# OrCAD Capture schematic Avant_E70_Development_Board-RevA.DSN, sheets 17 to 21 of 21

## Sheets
17 Power Supplies 2: size D; title: Power Supplies 2
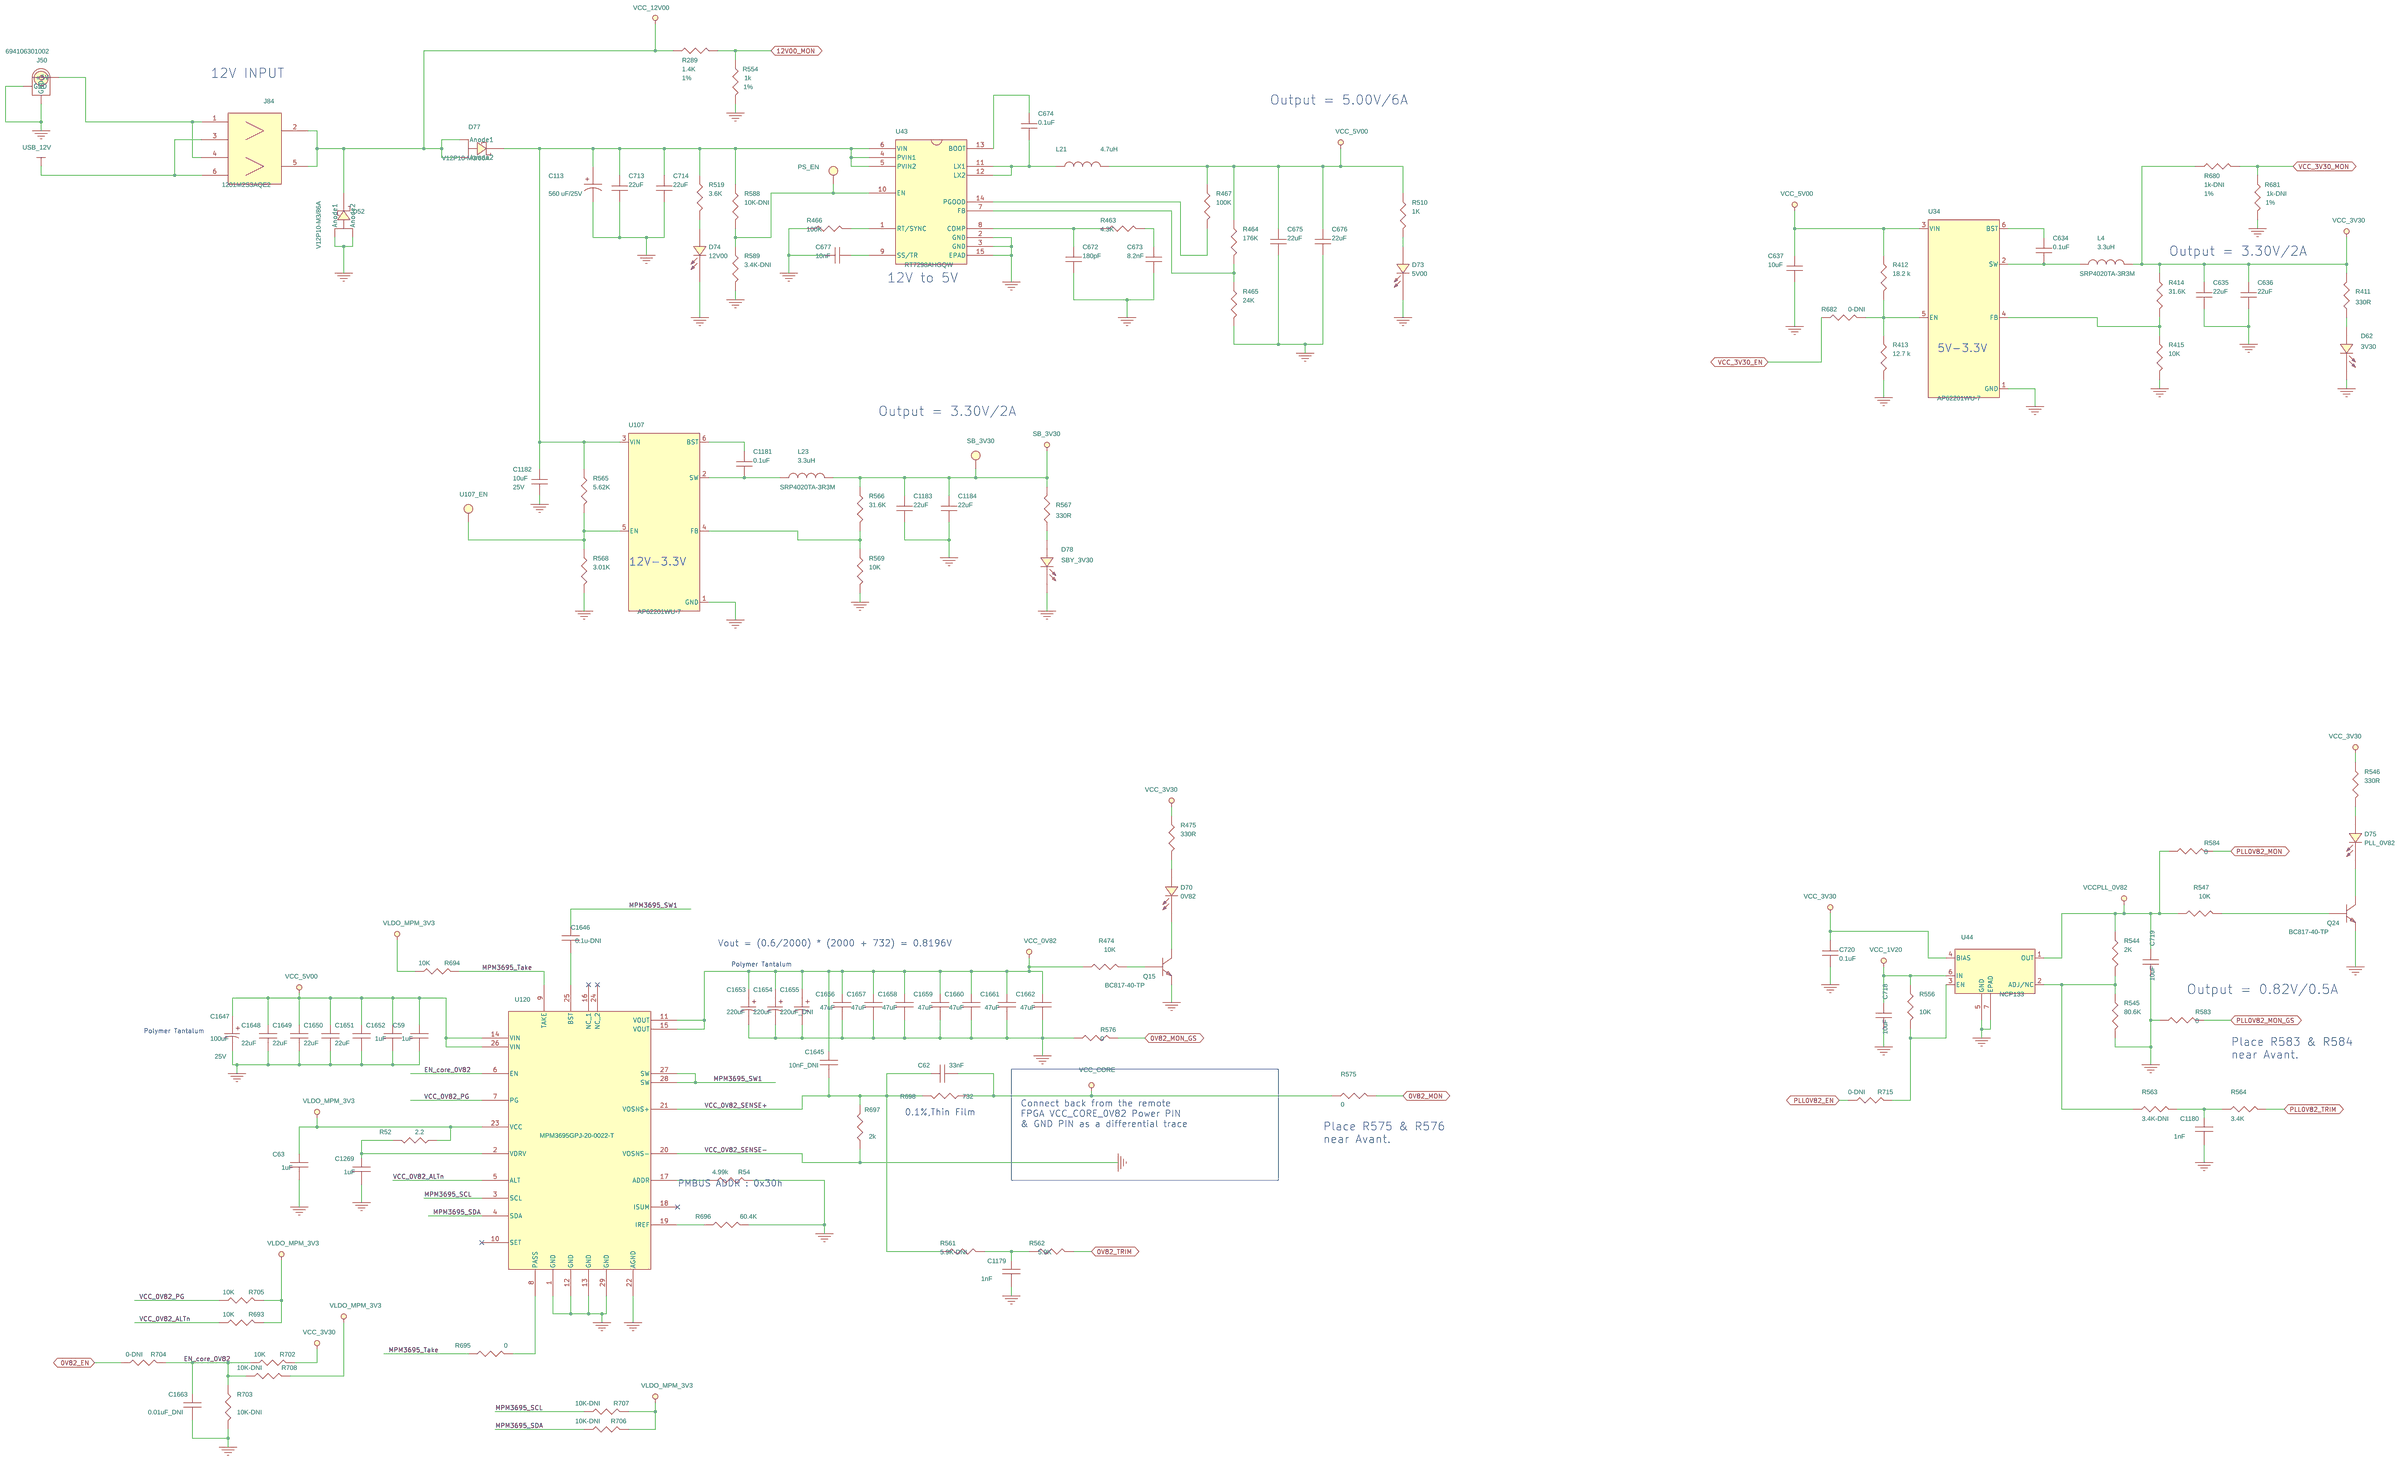
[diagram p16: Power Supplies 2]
18 Ground: size B; title: Ground
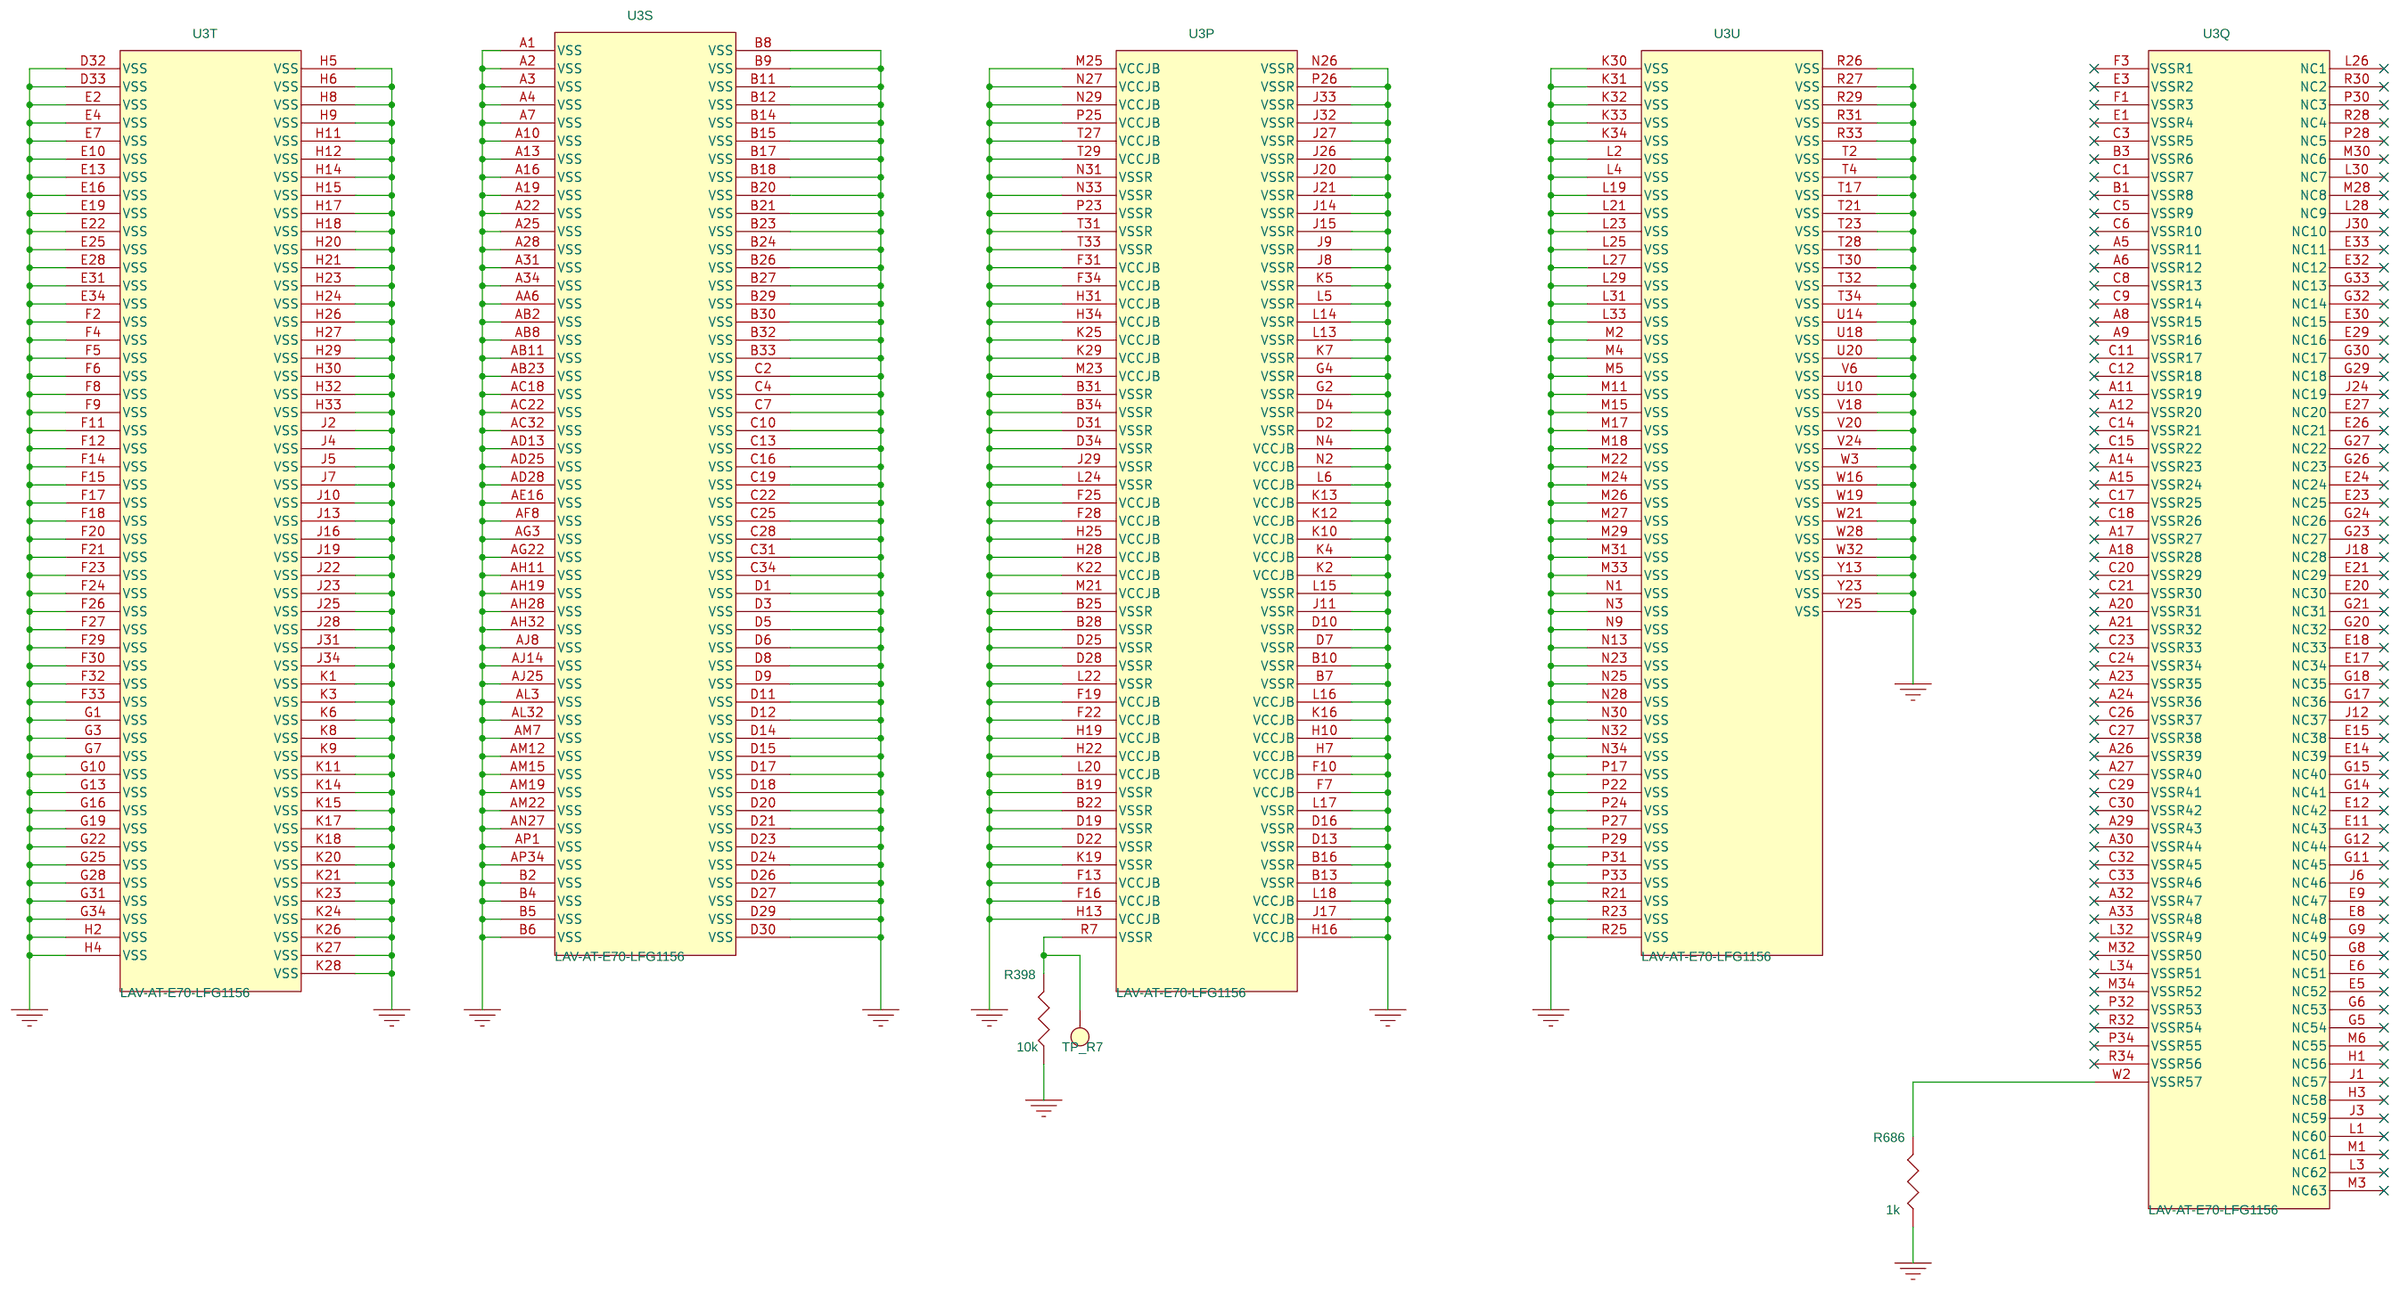
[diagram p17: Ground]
19 Platform Manager 2: size C; title: Platfrom Manager 2
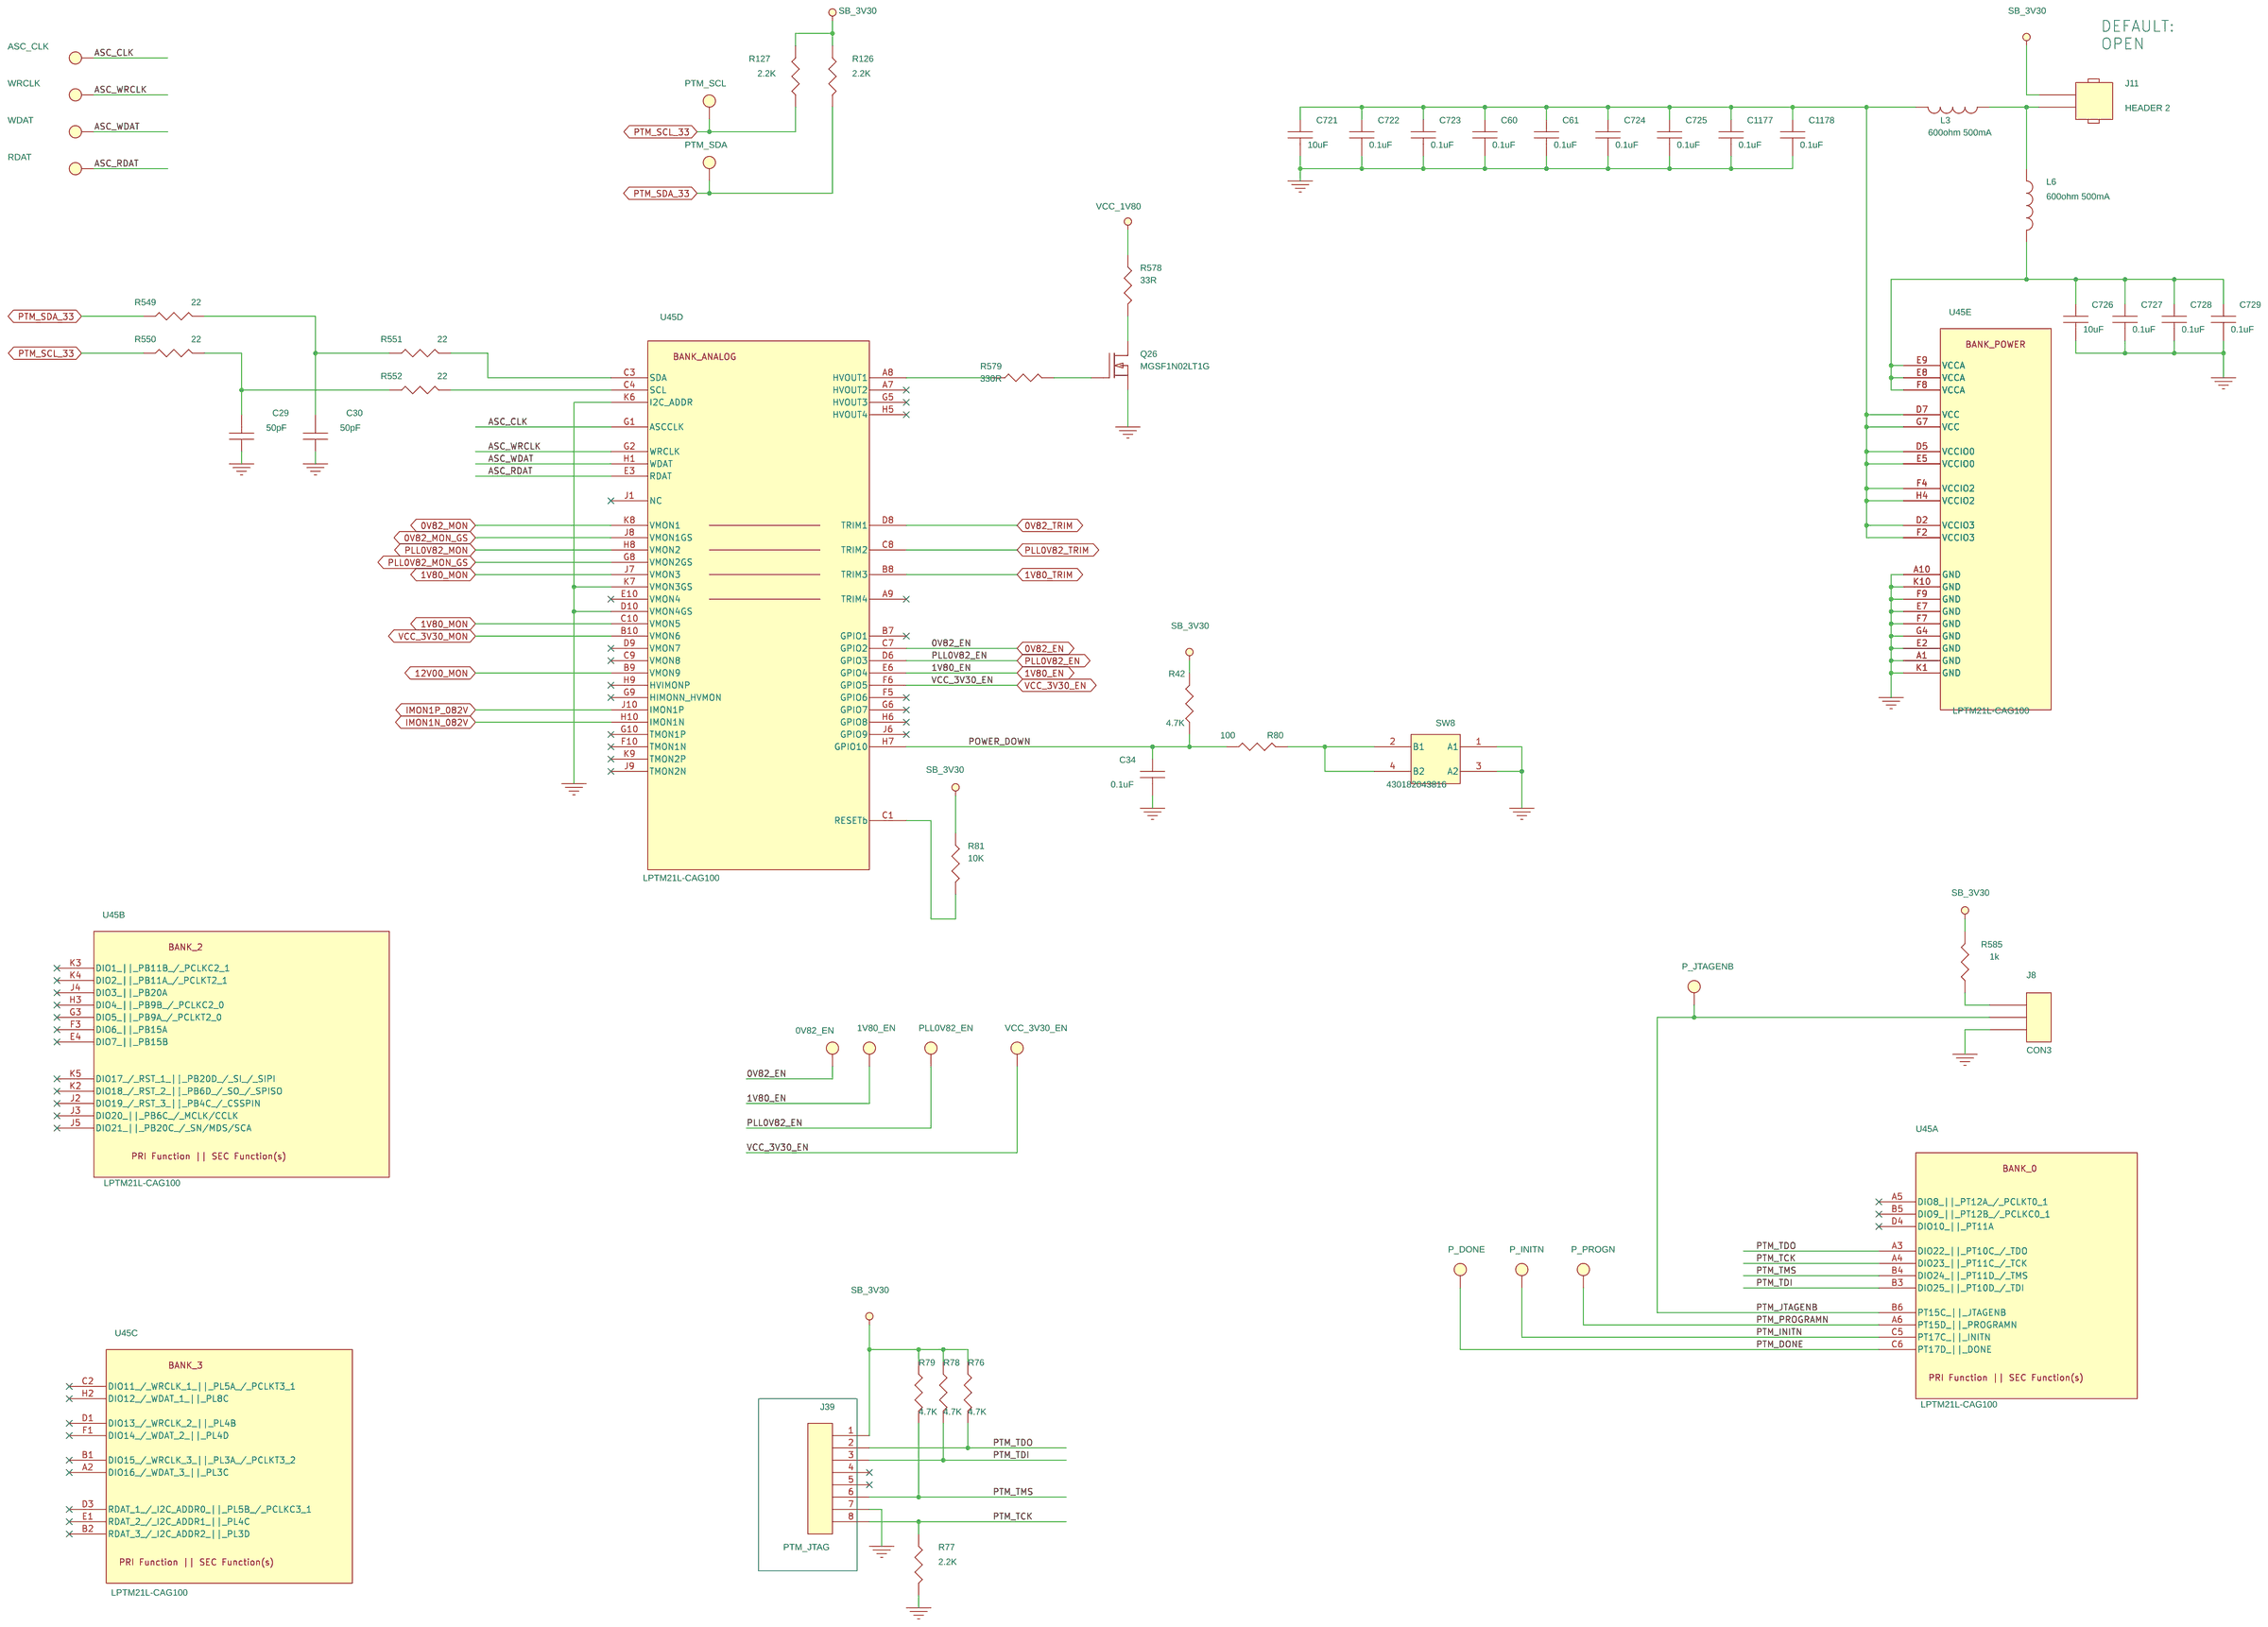
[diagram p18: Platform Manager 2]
20 USB Power Sink: size B; title: USB Power Sink
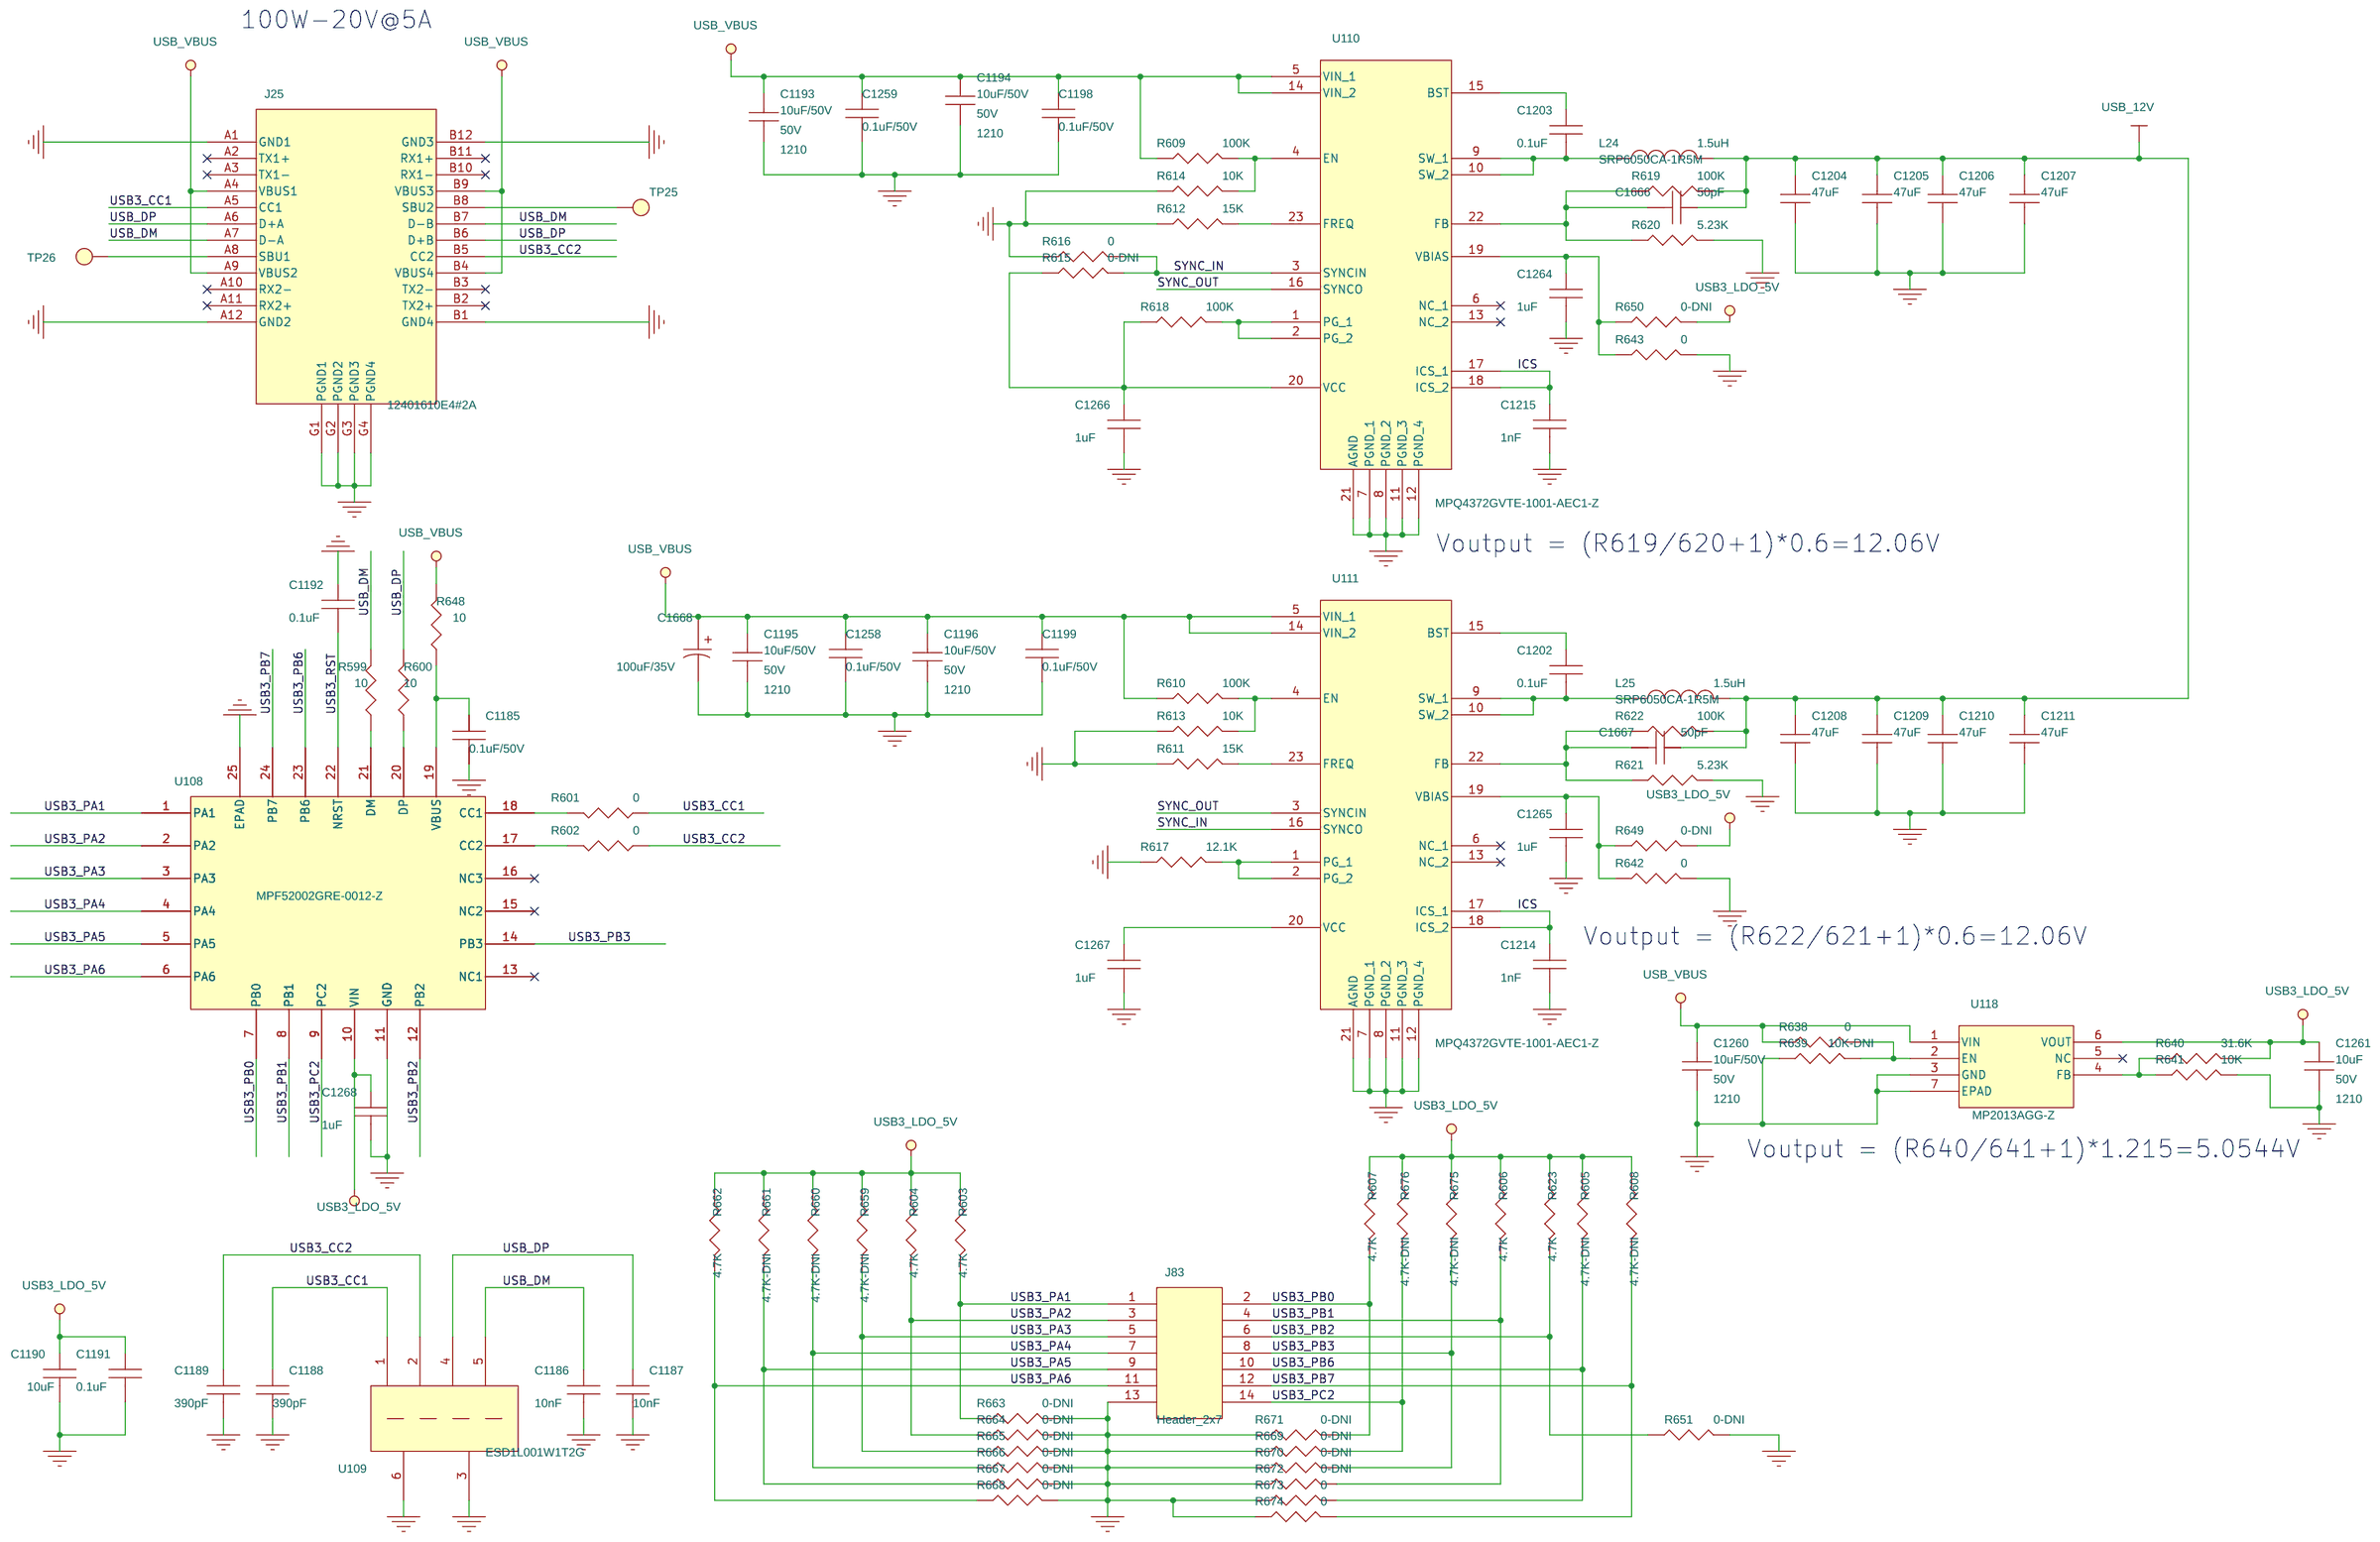
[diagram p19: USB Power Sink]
21 Power Block Diagram: title: Power Block Diagram
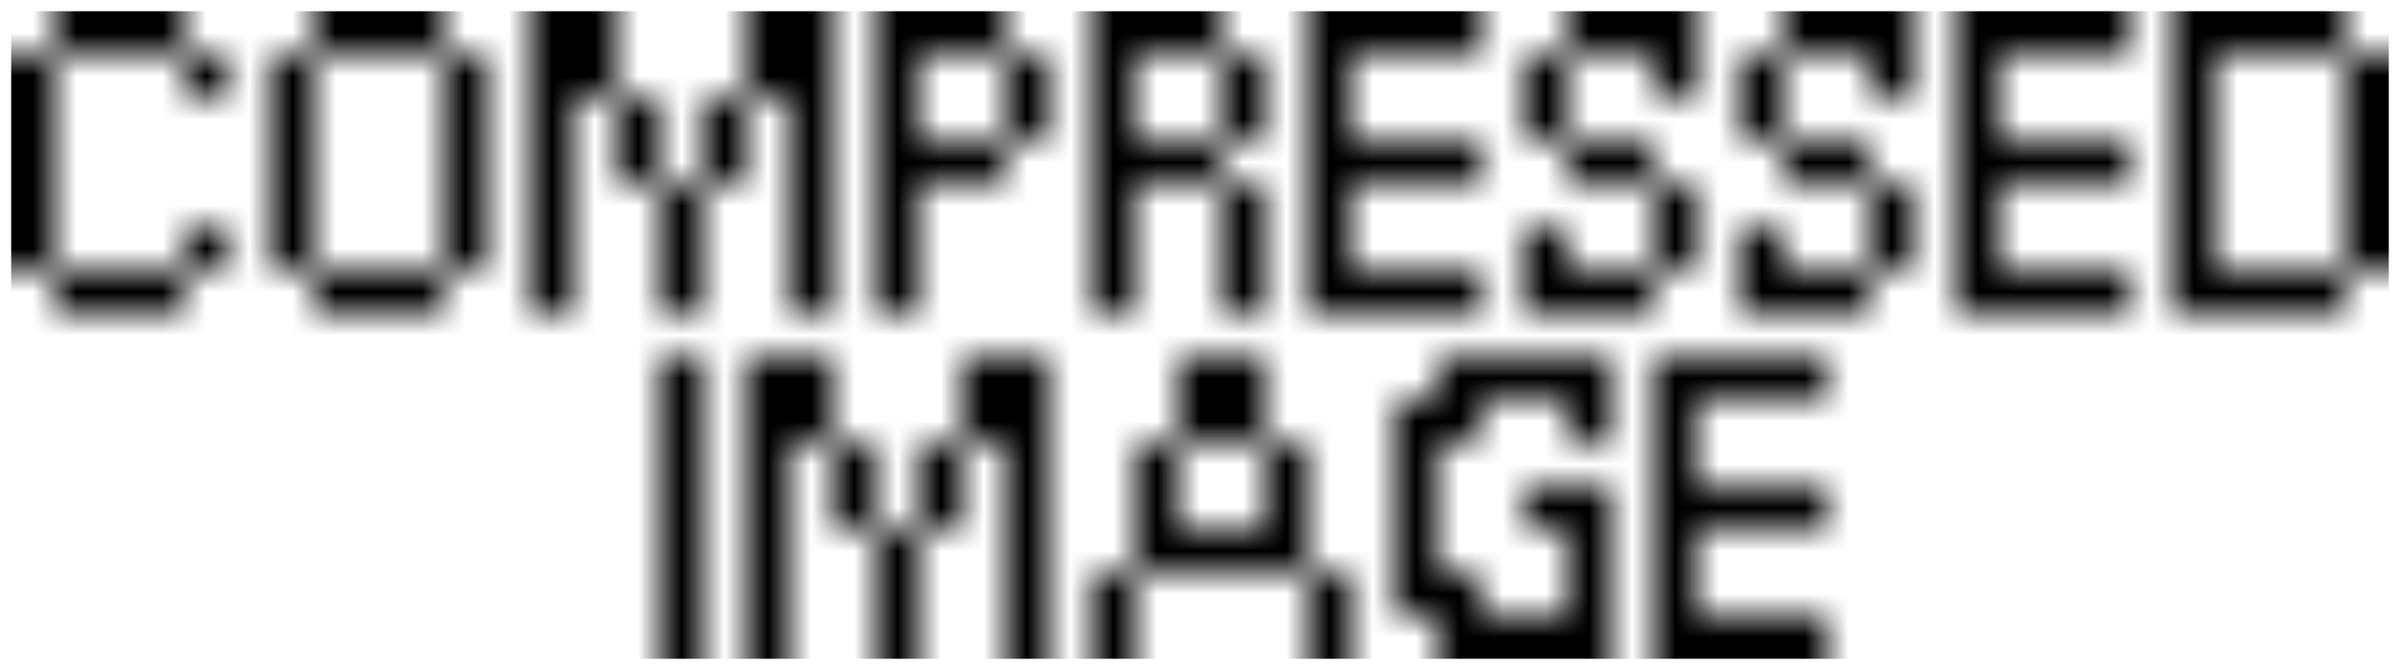
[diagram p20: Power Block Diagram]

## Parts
sheet Bank-12,13 PMODs
U3  LAV-AT-E70-LFG1156  [LAV-AT-500-L_1156]  (sections A,B,C,D,E,F,G,H,I,J,K,L,M,N,O,P,Q,R,S,T,U)
sheet Ground
R398  10k  [R0402]
R686  1k  [R0402]
TP_R7  T POINT R  [TP]
sheet Platform Manager 2
0V82_EN  T POINT R  [TP]
1V80_EN  T POINT R  [TP]
ASC_CLK  VTTVREF  [TP_50]
C29  50pF  [C0603]
C30  50pF  [C0603]
C34  0.1uF  [C0201]
C60  0.1uF  [C0402]
C61  0.1uF  [C0402]
C721  10uF  [C0402]
C722  0.1uF  [C0402]
C723  0.1uF  [C0402]
C724  0.1uF  [C0402]
C725  0.1uF  [C0402]
C726  10uF  [C0402]
C727  0.1uF  [C0402]
C728  0.1uF  [C0402]
C729  0.1uF  [C0402]
C1177  0.1uF  [C0402]
C1178  0.1uF  [C0402]
J8  CON3  [HDR1X3]
J11  HEADER 2  [22284024]
J39  PTM_JTAG  [hdr_amp_87220_8_1x8_100]
L3  600ohm 500mA  [fb0603]
L6  600ohm 500mA  [fb0603]
P_DONE  VTTVREF  [TP_50]
P_INITN  VTTVREF  [TP_50]
P_JTAGENB  VTTVREF  [TP_50]
P_PROGN  VTTVREF  [TP_50]
PLL0V82_EN  T POINT R  [TP]
PTM_SCL  VTTVREF  [TP_50]
PTM_SDA  VTTVREF  [TP_50]
Q26  MGSF1N02LT1G  [SOT23_MGSF1N02L]
R42  4.7K  [R0603]
R76  4.7K  [R0603]
R77  2.2K  [R0603]
R78  4.7K  [R0603]
R79  4.7K  [R0603]
R80  100  [R0402]
R81  10K  [R0603]
R126  2.2K  [R0603]
R127  2.2K  [R0603]
R549  22  [R0402]
R550  22  [R0402]
R551  22  [R0402]
R552  22  [R0402]
R578  33R  [0603]
R579  330R  [R0603]
R585  1k  [R0402]
RDAT  VTTVREF  [TP_50]
SW8  430182043816  [430182043816]
U45  LPTM21L-CAG100  [LPTM21L-CAG100]  (sections A,B,C,D,E)
VCC_3V30_EN  T POINT R  [TP]
WDAT  VTTVREF  [TP_50]
WRCLK  VTTVREF  [TP_50]
sheet Power Supplies 2
C59  1uF  [C0402]
C62  33nF  [C0603]
C63  1uF  [C0402]
C113  560 uF/25V  [RAD_CAN_A768MS]
C634  0.1uF  [C0402]
C635  22uF  [C0603]
C636  22uF  [C0603]
C637  10uF  [C0603]
C672  180pF  [C0402]
C673  8.2nF  [C0402]
C674  0.1uF  [C0402]
C675  22uF  [C0603]
C676  22uF  [C0603]
C677  10nF  [C0402]
C713  22uF  [C0603]
C714  22uF  [C0603]
C718  10uF  [C0603]
C719  10uF  [C0603]
C720  0.1uF  [C0402]
C1179  1nF  [C0603]
C1180  1nF  [C0603]
C1181  0.1uF  [C0402]
C1182  10uF  [C0603]
C1183  22uF  [C0603]
C1184  22uF  [C0603]
C1269  1uF  [C0402]
C1645  10nF_DNI  [C0402]
C1646  0.1u-DNI  [C0603]
C1647  100uF  [TC7343]
C1648  22uF  [C0805]
C1649  22uF  [C0805]
C1650  22uF  [C0805]
C1651  22uF  [C0805]
C1652  1uF  [C0402]
C1653  220uF  [TC7343]
C1654  220uF  [TC7343]
C1655  220uF_DNI  [TC7343]
C1656  47uF  [C0805]
C1657  47uF  [C0805]
C1658  47uF  [C0805]
C1659  47uF  [C0805]
C1660  47uF  [C0805]
C1661  47uF  [C0805]
C1662  47uF  [C0805]
C1663  0.01uF_DNI  [C0402]
D52  V12P10-M3/86A  [TO-277A]
D62  3V30  [APT1608]
D70  0V82  [APT1608]
D73  5V00  [APT1608]
D74  12V00  [APT1608]
D75  PLL_0V82  [APT1608]
D77  V12P10-M3/86A  [TO-277A]
D78  SBY_3V30  [APT1608]
J50  694106301002  [694106301002]
J84  1201M2S3AQE2  [1201M2S3AQE2]
L4  3.3uH  [SRP4020TA-3R3M]
L21  4.7uH  [8mmx8mm]
L23  3.3uH  [SRP4020TA-3R3M]
PS_EN  TestPoint_SMT  [TPC32]
Q15  BC817-40-TP  [SOT23-3]
Q24  BC817-40-TP  [SOT23-3]
R52  2.2  [R0603]
R54  4.99k  [R0402]
R289  1.4K  [R0603]
R411  330R  [R0603]
R412  18.2 k  [res0402]
R413  12.7 k  [res0402]
R414  31.6K  [R0603]
R415  10K  [0603]
R463  4.3K  [0603]
R464  176K  [0603]
R465  24K  [0603]
R466  100K  [R0603]
R467  100K  [R0603]
R474  10K  [R0603]
R475  330R  [R0603]
R510  1K  [R0402]
R519  3.6K  [R0402]
R544  2K  [R0603]
R545  80.6K  [0603]
R546  330R  [R0603]
R547  10K  [R0603]
R554  1k  [R0603]
R556  10K  [R0603]
R561  5.9K-DNI  [0603]
R562  5.9K  [0603]
R563  3.4K-DNI  [0603]
R564  3.4K  [0603]
R565  5.62K  [0603]
R566  31.6K  [R0603]
R567  330R  [R0603]
R568  3.01K  [0402]
R569  10K  [R0603]
R575  0  [R0402]
R576  0  [R0402]
R583  0  [R0402]
R584  0  [R0402]
R588  10K-DNI  [R0603]
R589  3.4K-DNI  [0603]
R680  1k-DNI  [R0603]
R681  1k-DNI  [R0603]
R682  0-DNI  [R0603]
R693  10K  [R0402]
R694  10K  [R0402]
R695  0  [R0402]
R696  60.4K  [R0603]
R697  2k  [R0603]
R698  732  [R0603]
R702  10K  [R0402]
R703  10K-DNI  [R0402]
R704  0-DNI  [R0402]
R705  10K  [R0402]
R706  10K-DNI  [R0402]
R707  10K-DNI  [R0402]
R708  10K-DNI  [R0603]
R715  0-DNI  [R0402]
SB_3V30  T POINT R  [TP]
U34  AP62201WU-7  [TSOT26_AP62201WU-7]
U43  RT7298AHGQW  [14-WQFN]
U44  NCP133  [XFDFN6]
U107  AP62201WU-7  [TSOT26_AP62201WU-7]
U107_EN  T POINT R  [TP]
U120  MPM3695GPJ-20-0022-T  [ECLGA-29-5x6x4r4]
sheet USB Power Sink
C1185  0.1uF/50V  [C0805]
C1186  10nF  [C0402]
C1187  10nF  [C0402]
C1188  390pF  [C0201]
C1189  390pF  [C0201]
C1190  10uF  [C0402]
C1191  0.1uF  [C0201]
C1192  0.1uF  [C0201]
C1193  10uF/50V  [C1210]
C1194  10uF/50V  [C1210]
C1195  10uF/50V  [C1210]
C1196  10uF/50V  [C1210]
C1198  0.1uF/50V  [C0402]
C1199  0.1uF/50V  [C0402]
C1202  0.1uF  [C0201]
C1203  0.1uF  [C0201]
C1204  47uF  [C1210]
C1205  47uF  [C1210]
C1206  47uF  [C1210]
C1207  47uF  [C1210]
C1208  47uF  [C1210]
C1209  47uF  [C1210]
C1210  47uF  [C1210]
C1211  47uF  [C1210]
C1214  1nF  [C0603]
C1215  1nF  [C0603]
C1258  0.1uF/50V  [C0402]
C1259  0.1uF/50V  [C0402]
C1260  10uF/50V  [C1210]
C1261  10uF  [C0603]
C1264  1uF  [C0603]
C1265  1uF  [C0603]
C1266  1uF  [C0603]
C1267  1uF  [C0603]
C1268  1uF  [C0603]
C1666  50pF  [C0603]
C1667  50pF  [C0603]
C1668  100uF/35V  [7360-20]
J25  12401610E4#2A  [USB_TYPEC_RA_SMT]
J83  Header_2x7  [Header_2x7]
L24  1.5uH  [L6R6X6R4-4R8]
L25  1.5uH  [L6R6X6R4-4R8]
R599  10  [R0402]
R600  10  [R0402]
R601  0  [R0402]
R602  0  [R0402]
R603  4.7K  [R0603]
R604  4.7K  [R0603]
R605  4.7K-DNI  [R0603]
R606  4.7K  [R0603]
R607  4.7K  [R0603]
R608  4.7K-DNI  [R0603]
R609  100K  [R0603]
R610  100K  [R0603]
R611  15K  [R0603]
R612  15K  [R0603]
R613  10K  [R0603]
R614  10K  [R0603]
R615  0-DNI  [R0603]
R616  0  [R0603]
R617  12.1K  [R0603]
R618  100K  [R0603]
R619  100K  [R0603]
R620  5.23K  [R0603]
R621  5.23K  [R0603]
R622  100K  [R0603]
R623  4.7K  [R0603]
R638  0  [R0603]
R639  10K-DNI  [R0603]
R640  31.6K  [R0603]
R641  10K  [R0603]
R642  0  [R0603]
R643  0  [R0603]
R648  10  [R0402]
R649  0-DNI  [R0603]
R650  0-DNI  [R0603]
R651  0-DNI  [R0603]
R659  4.7K-DNI  [R0603]
R660  4.7K-DNI  [R0603]
R661  4.7K-DNI  [R0603]
R662  4.7K  [R0603]
R663  0-DNI  [R0603]
R664  0-DNI  [R0603]
R665  0-DNI  [R0603]
R666  0-DNI  [R0603]
R667  0-DNI  [R0603]
R668  0-DNI  [R0603]
R669  0-DNI  [R0603]
R670  0-DNI  [R0603]
R671  0-DNI  [R0603]
R672  0-DNI  [R0603]
R673  0  [R0603]
R674  0  [R0603]
R675  4.7K-DNI  [R0603]
R676  4.7K-DNI  [R0603]
TP25  TestPoint_SMT  [TPC32]
TP26  TestPoint_SMT  [TPC32]
U108  MPF52002GRE-0012-Z  [QFN24N4X4P0_5]
U109  ESD1L001W1T2G  [SC-88]
U110  MPQ4372GVTE-1001-AEC1-Z  [QFN-23]
U111  MPQ4372GVTE-1001-AEC1-Z  [QFN-23]
U118  MP2013AGG-Z  [QFN6-MP2013]

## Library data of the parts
U3 = LAV-AT-E70-LFG1156_6
R398 R686 = RES_10K_1W16_0402_5P: RES SMD 10K OHM 1% 1/16W 0402; Digikey P/N: 311-10.0KLRTR-ND; Manufacturer: Yageo; Manufacturer Part Number: RC0402FR-0710KL
0V82_EN 1V80_EN PLL0V82_EN SB_3V30 TP_R7 U107_EN VCC_3V30_EN = T_POINT_R_0: Assy: DNI; COMPFIXED: NO; COMPGROUP: 0; COMPHEIGHT: 0.000; COMPKEY: NO; COMPLOC: [500.000,3800.000]; COMPLOCKED: NO; COMPROT: 0; COMPSIDE: TOP; DECOUPLER: NO; MEMORY: NO
ASC_CLK P_DONE P_INITN P_JTAGENB P_PROGN PTM_SCL PTM_SDA RDAT WDAT WRCLK = TP_SMD
C29 C30 C1666 C1667 = 0u1_0402: Digikey P/N: C0402C180K3GACTU-ND
C34 = 0u1_0402: CAP CER 0.1UF 16V 10% X7R 0402
C60 C61 C721-C729 C1177-C1180 = 0u1_0402
J8 = CON3
J11 = HEADER_2
J39 = header1x8_100: CONN HEADER 8POS .100 VERT TIN; Digikey P/N: WM50017-08-ND; Manufacturer Part Number: 22284081
L3 L6 = FB0603_0
Q26 = 2N3796_0: MOSFET N-CH 20V 750MA SOT23-3; Manufacturer: Onsemi
R42 R76 R78 R79 R603-R623 R638-R643 R649-R651 R659-R676 = 5k1_0402: RES 4.70K OHM 1/10W 1% 0603 SMD; Digikey P/N: 541-4.70KHTR-ND; Manufacturer: Vishay; Manufacturer Part Number: CRCW06034K70FKEA
R77 = 5k1_0402: Digikey P/N: 541-2.20KHTR-ND; Manufacturer: Vishay; Manufacturer Part Number: CRCW06032K20FKEA
R80 = RES_10K_1W16_0402_5P: RES SMD 100 OHM 1% 1/10W 0402; Digikey P/N: RMCF0603JT10K0TR-ND; MFG: Pansonic; MFG P/N: ERJ-2RKF1000X; Manufacturer: Pansonic; Manufacturer Part Number: ERJ-2RKF1000X; Wattage: 1/10W
R81 = RES_10K_1W16_0402_5P: Digikey P/N: RMCF0603JT10K0TR-ND; Manufacturer Part Number: RMCF0402JT10K0; Wattage: 1/10W
R126 R127 R549-R552 = 10k_0402: Digikey P/N: 311-12.0KHRTR-ND; Tolerance: 1%
R578 = R0603_33R_5%_Yageo
R579 = R0402_330R
R585 = RES_100K_1W16_0402_5P: RES SMD 1K OHM 1% 1/16W 0402; Digikey P/N: 311-1.00KLRTR-ND; Manufacturer: Yageo; Manufacturer Part Number: RC0402FR-071KL
SW8 = EVQP0_0: SWITCH TACTILE SPST-NO 0.05A 12V; Cost Ea/1k: $ 0.11025 (1000-4999), 0.09135 (5000+); Digikey P/N: CKN9112TR-ND; Distributor: Digi-Key; MFG: C&K Components; Manufacturer: C&K Components
U45 = LPTM21L-CAG100
C59 C63 C1269 C1652 = 10uF_0603: MLCC - SMD/SMT 1 uF 25 VDC 10% 0402 X5R; Manufacturer: Murata; Manufacturer Part Number: GRM155R61E105KA12D; Part Number: GRM155R61E105KA12D; Voltage: 25V
C62 = 10uF_0603: MLCC - SMD/SMT 50V 0.033uF X7R 0603 10%; Manufacturer: Kemet; Manufacturer Part Number: C0603C333K5RACTU; Part Number: C0603C333K5RACTU; Voltage: 25V
C113 = CAP_POL: CAP ALUM POLY 560UF 20% 25V SMD; Manufacturer: KEMET; Manufacturer Part Number: A768MS567M1ELAS017
C634 C674 C1181 = C_0.1uF_50V_CER_0402: Manufacturer Part Number: GRM155R71H104KE14J
C635 C636 C675 C676 C1183 C1184 = C-0603_22uF_10V_X5R_Samsung: Manufacturer Part Number: CL10A226MP8NUNE
C637 = C-0603_10uF_16V_X5R_TaiyoYuden: Manufacturer Part Number: EMK107BBJ106MA-T
C672 = C-0402_180P: Manufacturer Part Number: 04025C181KAT2A
C673 = C-0402_8n2F_25V_X7R_MURATA: Manufacturer Part Number: GRM155R71E822KA01D
C677 = C-0402_10nF_16V_X7R_YAGEO: Manufacturer Part Number: CC0402KRX7R7BB103
C713 C714 C1204-C1211 = C-0805_22uF_25V_X5R_Yageo: Manufacturer Part Number: CC0805MKX5R8BB226
C718 C719 = C_10uf_CER_25V_0603: CAP CER 10UF 25V X5R 0805; Manufacturer: TDK Corporation; Manufacturer Part No: C2012X5R1E106M085AC; Manufacturer Part Number: C2012X5R1E106M085AC
C720 = C-0402_0.1uF_10V_X5R_MURATA
C1182 = C-0603_10uF_16V_X5R_TaiyoYuden: CAP CER 10UF 25V X5R 0603; MFG: TDK Corporation; MFG P/N: C1608X5R1E106M080AC; Manufacturer Part Number: C1608X5R1E106M080AC; Voltage: 25V
C1645 C1663 = 10uF_0603: MLCC - SMD/SMT 0.01 uF 25 VDC 10% 0402 X7R AEC-Q200; Manufacturer: Murata; Manufacturer Part Number: GCM155R71E103KA37D; Part Number: GCM155R71E103KA37D; Voltage: 25V
C1646 = 10uF_0603: MLCC - SMD/SMT 2.2 uF 10 VDC 10% 0603 X7R; Manufacturer: Murata; Manufacturer Part Number: GRM188R71A225KE15D; Part Number: GRM188R71A225KE15D; Voltage: 10V
C1647 = CAP_Electrolytic_SMD_OSCON_E7: T521, Polymer Tantalum, 100 uF, 20%, 25 VDC, SMD, Polymer,ESR=60mohm; Manufacturer: Kemet; Manufacturer Part Number: T521X107M025ATE060; Part Number: T521X107M025ATE060; Voltage: 25V
C1648-C1651 = 10uF_0603: MLCC - SMD/SMT 22 uF 25 VDC 20% 0805 X5R; Manufacturer: Murata; Manufacturer Part Number: GRM21BR61E226ME44L; Part Number: GRM21BR61E226ME44L; Voltage: 25V
C1653-C1655 = CAP_Electrolytic_SMD_OSCON_E7: Polymer Tantalum, 2.5V 220uF 7343 20% ESR=0.009Ohms; Manufacturer: Kemet; Manufacturer Part Number: T598D227M2R5ATE009; Part Number: T598D227M2R5ATE009; Voltage: 2.5V
C1656-C1662 = 10uF_0603: MLCC - SMD/SMT 47 uF 6.3 VDC 20% 0805 X5R; Manufacturer: Murata; Manufacturer Part Number: GRM219R60J476ME44D; Part Number: GRM219R60J476ME44D; Voltage: 6.3V
D52 D77 = TMP_0
D62 D70 D73-D75 D78 = LED_GREEN_0: Manufacturer Part Number: SML-D12M8WT86
J50 = J_JACK_2.10mm
J84 = 1201M2S3AQE2
L4 L23 = INDUCTOR_0: FIXED IND 3.3UH 3.5A 76 MOHM SMD; Manufacturer: Bourns Inc.
L21 = L-4u7H_4.1A_TaiyoYuden
PS_EN TP25 TP26 = T_POINT_R: Assy: DNI
Q15 Q24 = TRANS_NPN_45V_0_0.8A_SOT-23: TRANS NPN 45V 0.8A SOT-23; Manufacturer: Micro Commercial Co
R52 = 0R_0603: SMD 2.2 Ohms 100mW 0603 1%; Manufacturer: Yageo; Manufacturer Part Number: RC0603FR-072R2L; Part Number: RC0603FR-072R2L
R54 = RES_1K_1W16_0402_5P: SMD 4.99 kOhms 62.5mW 0402 1%; Manufacturer: Yageo; Manufacturer Part Number: RC0402FR-074K99L; Part Number: RC0402FR-074K99L
R289 R554 R680 R681 = 10k_0402: Tolerance: 1%
R411 R475 R546 R567 = R_330R_0603: Manufacturer Part Number: ERJ-3EKF3300V
R412 = R_42.2K_0402: RES SMD 18.2KOHM 0.1% 1/16W 0402; Manufacturer: YAGEO; Manufacturer Part No: RT0402BRD0718K2L; Manufacturer Part Number: RT0402BRD0718K2L
R413 = R_12.7K_0402: Manufacturer Part Number: ERJ-2RKF1272X
R414 R566 = R0603_31K6_1%_Yageo
R415 R569 = R0603_10K_1%_Yageo: Manufacturer Part Number: RC0603FR-0710KL
R463 = R0603_4K3_1%_Yageo: Manufacturer Part Number: RC0603FR-074K3L
R464 = R0603_176K_0.5%_Yageo: Manufacturer Part Number: RT0603DRE07176KL
R465 = R0603_24K_1%_Yageo: Manufacturer Part Number: RC0603FR-0724KL
R466 R467 = R0603_100K_1%_Yageo: Manufacturer Part Number: RC0603FR-07100KL
R474 R547 = R_10K_0603: Manufacturer Part Number: RC1608F103CS
R510 = R0402_1K_5%_VISHAY: Manufacturer Part Number: CRCW04021K00JNED
R519 = R0402_3K6_5%_YAGEO: Manufacturer Part Number: RC0402JR-073K6L
R544 = R0603_2K_1%_Yageo
R545 = R0603_80K6_1%_Yageo
R556 = R0603_10K_5%_Yageo
R561 R562 = R0603_5K9_1%_Yageo
R563 R564 = R0603_3K4_1%_Yageo
R565 = R0603_5K62_1%_Yageo
R568 = R0402_3K_1%_Yageo
R575 R576 R583 R584 = R0402_0R_5%_PANASONIC
R588 R589 = R0603_NP
R682 R708 = R0603_10K_1%_Yageo
R693 R694 R702 R703 R705-R707 = RES_1K_1W16_0402_5P: SMD 10 kOhms 62.5mW 0402 1%; Manufacturer: Yageo; Manufacturer Part Number: RC0402FR-0710KL; Part Number: RC0402FR-0710KL
R695 R704 R715 = 0R_0603: Thick Film Resistors - SMD 0402 Zero Ohms; Manufacturer: Vishay / Dale; Manufacturer Part Number: CRCW04020000ZSTD; Part Number: Part Number
R696 = 0R_0603: SMD 60.4 kOhms 100mW 0603 1%; Manufacturer: Yageo; Manufacturer Part Number: RC0603FR-0760K4L; Part Number: RC0603FR-0760K4L
R697 = RES_1K_1W16_0402_5P: Thin film chip resistor SMD 2K OHM .1% 25PPM; Manufacturer: Yageo; Manufacturer Part Number: RT0603BRD072KL; Part Number: RT0603BRD072KL
R698 = RES_1K_1W16_0402_5P: Thin film chip resistor  SMD CPF 0603 732R 0.1% 25PPM; Manufacturer: TE Connectivity; Manufacturer Part Number: CPF0603B732RE1; Part Number: CPF0603B732RE1
U34 U107 = U-AP62201WU-7
U43 = U-RT7298AHGQW_Richtek
U44 = U-NCP133_LDOR_1: Manufacturer Part Number: NCP133AMXADJTCG
U120 = MPM3695-20_0
C1185-C1189 C1191 C1192 C1198 C1199 C1202 C1203 C1214 C1215 C1258 C1259 = 0u1_0402: CAP CER 0.1UF 25V 10% X5R 0201; Manufacturer: Murata; Manufacturer Part Number: GRM033R61E104KE14J
C1190 = 10uF_0603: CAP CER 10UF 10V 20% X5R 0603
C1193-C1196 C1260 C1261 = C-0805_22uF_25V_X5R_Yageo: Manufacturer Part Number: CC0805MKX5R8BB226; Package: 1210; Voltage: 50V
C1264-C1268 = 10uF_0603: CAP CER 1UF 25V 10% X7R 0603; Manufacturer Part Number: TMK107B7105KA-T
C1668 = CAP_Electrolytic_SMD_OSCON_E7: T521, 100uF 35volts 20% 55mohms maxESR; Manufacturer: Vishay; Manufacturer Part Number: T52M1107M035C0055; Part Number: T52M1107M035C0055; Voltage: 35V
J25 = USB_TYPEC_SMT: USB TYPE C RCPT R/A SMT TOP MOUNT; Manufacturer: Amphenol
J83 = Header_2x7
L24 L25 = L-4u7H_4.1A_TaiyoYuden: MFG P/N: SRP6050CA-1R5M
R599-R602 R648 = R_v2: RES SMD 33 OHM 1% 1/10W 0402; Manufacturer: Panasonic; Manufacturer Part Number: ERJ-2RKF33R0X
U108 = MPF52002
U109 = ESD1L001
U110 U111 = MPQ4371
U118 = MP2013A

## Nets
0V82_EN: 0V82_EN.1(TP) R704.2 U45.C7(GPIO2)
0V82_MON: R575.2 U45.K8(VMON1)
0V82_MON_GS: R576.2 U45.J8(VMON1GS)
0V82_TRIM: R562.2 U45.D8(TRIM1)
1V80_EN: 1V80_EN.1(TP) U45.E6(GPIO4) ; also on sheet 16
1V80_MON: U45.C10(VMON5) U45.J7(VMON3) ; also on sheet 16
1V80_TRIM: U45.B8(TRIM3) ; also on sheet 16
12V00_MON: R289.1 R554.2 U45.B9(VMON9)
GND: C29.1 C30.1 C34.2 C59.2 C60.2 C61.2 C63.2 C113.2 C635.2 C636.2 C637.2 C672.2 C673.2 C675.2 C676.2 C677.1 C713.2 C714.2 C718.2 C719.2 C720.2 C721.2 C722.2 C723.2 C724.2 C725.2 C726.2 C727.2 C728.2 C729.2 C1177.2 C1178.2 C1179.2 C1180.2 C1182.2 C1183.2 C1184.2 C1185.2 C1186.2 C1187.2 C1188.2 C1189.2 C1190.2 C1191.2 C1192.1 C1193.2 C1194.2 C1195.2 C1196.2 C1198.2 C1199.2 C1204.2 C1205.2 C1206.2 C1207.2 C1208.2 C1209.2 C1210.2 C1211.2 C1214.2 C1215.2 C1258.2 C1259.2 C1260.2 C1261.2 C1264.2 C1265.2 C1266.2 C1267.2 C1268.2 C1269.2 C1647.2 C1648.2 C1649.2 C1650.2 C1651.2 C1652.2 C1653.2 C1654.2 C1655.2 C1656.2 C1657.2 C1658.2 C1659.2 C1660.2 C1661.2 C1662.2 C1663.2 C1668.2 D52.A1(Anode1) D52.A2(Anode2) D62.K D73.K D74.K D78.K J8.3 J25.A1(GND1) J25.A12(GND2) J25.B1(GND4) J25.B12(GND3) J25.G1(PGND1) J25.G2(PGND2) J25.G3(PGND3) J25.G4(PGND4) J39.7 J50.2(GND) J50.3(GND) J83.13 Q15.E Q24.E Q26.S R54.1 R77.2 R398.2 R413.2 R415.2 R465.2 R466.1 R545.2 R554.1 R568.2 R569.2 R576.1 R583.1 R589.2 R611.1 R612.1 R613.1 R614.1 R616.1 R617.1 R620.2 R621.2 R639.1 R641.2 R642.2 R643.2 R651.2 R663.2 R664.2 R665.2 R666.2 R667.2 R668.2 R669.1 R670.1 R671.1 R672.1 R673.1 R674.1 R681.1 R686.2 R696.2 R697.2 R703.1 SW8.1(A1) SW8.3(A2) U3.A1(VSS) U3.A2(VSS) U3.A3(VSS) U3.A4(VSS) U3.A7(VSS) U3.A10(VSS) U3.A13(VSS) U3.A16(VSS) U3.A19(VSS) U3.A22(VSS) U3.A25(VSS) U3.A28(VSS) U3.A31(VSS) U3.A34(VSS) U3.AA6(VSS) U3.AB2(VSS) U3.AB8(VSS) U3.AB11(VSS) U3.AB23(VSS) U3.AC18(VSS) U3.AC22(VSS) U3.AC32(VSS) U3.AD13(VSS) U3.AD25(VSS) U3.AD28(VSS) U3.AE16(VSS) U3.AF8(VSS) U3.AG3(VSS) U3.AG22(VSS) U3.AH11(VSS) U3.AH19(VSS) U3.AH28(VSS) U3.AH32(VSS) U3.AJ8(VSS) U3.AJ14(VSS) U3.AJ25(VSS) U3.AL3(VSS) U3.AL32(VSS) U3.AM7(VSS) U3.AM12(VSS) U3.AM15(VSS) U3.AM19(VSS) U3.AM22(VSS) U3.AN27(VSS) U3.AP1(VSS) U3.AP34(VSS) U3.B2(VSS) U3.B4(VSS) U3.B5(VSS) U3.B6(VSS) U3.B7(VSSR) U3.B8(VSS) U3.B9(VSS) U3.B10(VSSR) U3.B11(VSS) U3.B12(VSS) U3.B13(VSSR) U3.B14(VSS) U3.B15(VSS) U3.B16(VSSR) U3.B17(VSS) U3.B18(VSS) U3.B19(VSSR) U3.B20(VSS) U3.B21(VSS) U3.B22(VSSR) U3.B23(VSS) U3.B24(VSS) U3.B25(VSSR) U3.B26(VSS) U3.B27(VSS) U3.B28(VSSR) U3.B29(VSS) U3.B30(VSS) U3.B31(VSSR) U3.B32(VSS) U3.B33(VSS) U3.B34(VSSR) U3.C2(VSS) U3.C4(VSS) U3.C7(VSS) U3.C10(VSS) U3.C13(VSS) U3.C16(VSS) U3.C19(VSS) U3.C22(VSS) U3.C25(VSS) U3.C28(VSS) U3.C31(VSS) U3.C34(VSS) U3.D1(VSS) U3.D2(VSSR) U3.D3(VSS) U3.D4(VSSR) U3.D5(VSS) U3.D6(VSS) U3.D7(VSSR) U3.D8(VSS) U3.D9(VSS) U3.D10(VSSR) U3.D11(VSS) U3.D12(VSS) U3.D13(VSSR) U3.D14(VSS) U3.D15(VSS) U3.D16(VSSR) U3.D17(VSS) U3.D18(VSS) U3.D19(VSSR) U3.D20(VSS) U3.D21(VSS) U3.D22(VSSR) U3.D23(VSS) U3.D24(VSS) U3.D25(VSSR) U3.D26(VSS) U3.D27(VSS) U3.D28(VSSR) U3.D29(VSS) U3.D30(VSS) U3.D31(VSSR) U3.D32(VSS) U3.D33(VSS) U3.D34(VSSR) U3.E2(VSS) U3.E4(VSS) U3.E7(VSS) U3.E10(VSS) U3.E13(VSS) U3.E16(VSS) U3.E19(VSS) U3.E22(VSS) U3.E25(VSS) U3.E28(VSS) U3.E31(VSS) U3.E34(VSS) U3.F2(VSS) U3.F4(VSS) U3.F5(VSS) U3.F6(VSS) U3.F7(VCCJB) U3.F8(VSS) U3.F9(VSS) U3.F10(VCCJB) U3.F11(VSS) U3.F12(VSS) U3.F13(VCCJB) U3.F14(VSS) U3.F15(VSS) U3.F16(VCCJB) U3.F17(VSS) U3.F18(VSS) U3.F19(VCCJB) U3.F20(VSS) U3.F21(VSS) U3.F22(VCCJB) U3.F23(VSS) U3.F24(VSS) U3.F25(VCCJB) U3.F26(VSS) U3.F27(VSS) U3.F28(VCCJB) U3.F29(VSS) U3.F30(VSS) U3.F31(VCCJB) U3.F32(VSS) U3.F33(VSS) U3.F34(VCCJB) U3.G1(VSS) U3.G2(VSSR) U3.G3(VSS) U3.G4(VSSR) U3.G7(VSS) U3.G10(VSS) U3.G13(VSS) U3.G16(VSS) U3.G19(VSS) U3.G22(VSS) U3.G25(VSS) U3.G28(VSS) U3.G31(VSS) U3.G34(VSS) U3.H2(VSS) U3.H4(VSS) U3.H5(VSS) U3.H6(VSS) U3.H7(VCCJB) U3.H8(VSS) U3.H9(VSS) U3.H10(VCCJB) U3.H11(VSS) U3.H12(VSS) U3.H13(VCCJB) U3.H14(VSS) U3.H15(VSS) U3.H16(VCCJB) U3.H17(VSS) U3.H18(VSS) U3.H19(VCCJB) U3.H20(VSS) U3.H21(VSS) U3.H22(VCCJB) U3.H23(VSS) U3.H24(VSS) U3.H25(VCCJB) U3.H26(VSS) U3.H27(VSS) U3.H28(VCCJB) U3.H29(VSS) U3.H30(VSS) U3.H31(VCCJB) U3.H32(VSS) U3.H33(VSS) U3.H34(VCCJB) U3.J2(VSS) U3.J4(VSS) U3.J5(VSS) U3.J7(VSS) U3.J8(VSSR) U3.J9(VSSR) U3.J10(VSS) U3.J11(VSSR) U3.J13(VSS) U3.J14(VSSR) U3.J15(VSSR) U3.J16(VSS) U3.J17(VCCJB) U3.J19(VSS) U3.J20(VSSR) U3.J21(VSSR) U3.J22(VSS) U3.J23(VSS) U3.J25(VSS) U3.J26(VSSR) U3.J27(VSSR) U3.J28(VSS) U3.J29(VSSR) U3.J31(VSS) U3.J32(VSSR) U3.J33(VSSR) U3.J34(VSS) U3.K1(VSS) U3.K2(VCCJB) U3.K3(VSS) U3.K4(VCCJB) U3.K5(VSSR) U3.K6(VSS) U3.K7(VSSR) U3.K8(VSS) U3.K9(VSS) U3.K10(VCCJB) U3.K11(VSS) U3.K12(VCCJB) U3.K13(VCCJB) U3.K14(VSS) U3.K15(VSS) U3.K16(VCCJB) U3.K17(VSS) U3.K18(VSS) U3.K19(VSSR) U3.K20(VSS) U3.K21(VSS) U3.K22(VCCJB) U3.K23(VSS) U3.K24(VSS) U3.K25(VCCJB) U3.K26(VSS) U3.K27(VSS) U3.K28(VSS) U3.K29(VCCJB) U3.K30(VSS) U3.K31(VSS) U3.K32(VSS) U3.K33(VSS) U3.K34(VSS) U3.L2(VSS) U3.L4(VSS) U3.L5(VSSR) U3.L6(VCCJB) U3.L13(VSSR) U3.L14(VSSR) U3.L15(VSSR) U3.L16(VCCJB) U3.L17(VSSR) U3.L18(VCCJB) U3.L19(VSS) U3.L20(VCCJB) U3.L21(VSS) U3.L22(VSSR) U3.L23(VSS) U3.L24(VSSR) U3.L25(VSS) U3.L27(VSS) U3.L29(VSS) U3.L31(VSS) U3.L33(VSS) U3.M2(VSS) U3.M4(VSS) U3.M5(VSS) U3.M11(VSS) U3.M15(VSS) U3.M17(VSS) U3.M18(VSS) U3.M21(VCCJB) U3.M22(VSS) U3.M23(VCCJB) U3.M24(VSS) U3.M25(VCCJB) U3.M26(VSS) U3.M27(VSS) U3.M29(VSS) U3.M31(VSS) U3.M33(VSS) U3.N1(VSS) U3.N2(VCCJB) U3.N3(VSS) U3.N4(VCCJB) U3.N9(VSS) U3.N13(VSS) U3.N23(VSS) U3.N25(VSS) U3.N26(VSSR) U3.N27(VCCJB) U3.N28(VSS) U3.N29(VCCJB) U3.N30(VSS) U3.N31(VSSR) U3.N32(VSS) U3.N33(VSSR) U3.N34(VSS) U3.P17(VSS) U3.P22(VSS) U3.P23(VSSR) U3.P24(VSS) U3.P25(VCCJB) U3.P26(VSSR) U3.P27(VSS) U3.P29(VSS) U3.P31(VSS) U3.P33(VSS) U3.R21(VSS) U3.R23(VSS) U3.R25(VSS) U3.R26(VSS) U3.R27(VSS) U3.R29(VSS) U3.R31(VSS) U3.R33(VSS) U3.T2(VSS) U3.T4(VSS) U3.T17(VSS) U3.T21(VSS) U3.T23(VSS) U3.T27(VCCJB) U3.T28(VSS) U3.T29(VCCJB) U3.T30(VSS) U3.T31(VSSR) U3.T32(VSS) U3.T33(VSSR) U3.T34(VSS) U3.U10(VSS) U3.U14(VSS) U3.U18(VSS) U3.U20(VSS) U3.V6(VSS) U3.V18(VSS) U3.V20(VSS) U3.V24(VSS) U3.W3(VSS) U3.W16(VSS) U3.W19(VSS) U3.W21(VSS) U3.W28(VSS) U3.W32(VSS) U3.Y13(VSS) U3.Y23(VSS) U3.Y25(VSS) U34.1(GND) U43.2(GND) U43.3(GND) U43.15(EPAD) U44.5(GND) U44.7(EPAD) U45.A1(GND) U45.A10(GND) U45.D10(VMON4GS) U45.E2(GND) U45.E7(GND) U45.F7(GND) U45.F9(GND) U45.G4(GND) U45.K1(GND) U45.K6(I2C_ADDR) U45.K7(VMON3GS) U45.K10(GND) U107.1(GND) U108.11(GND) U108.25(EPAD) U109.3 U109.6 U110.7(PGND_1) U110.8(PGND_2) U110.11(PGND_3) U110.12(PGND_4) U110.21(AGND) U111.7(PGND_1) U111.8(PGND_2) U111.11(PGND_3) U111.12(PGND_4) U111.21(AGND) U118.3(GND) U118.7(EPAD) U120.1(GND) U120.12(GND) U120.13(GND) U120.20(VOSNS-) U120.22(AGND) U120.29(GND) ; also on sheet 3 4 5 6 7 8 9 10 11 12 13 14 15 16
VCC_0V82: C1645.1 C1653.1 C1654.1 C1655.1 C1656.1 C1657.1 C1658.1 C1659.1 C1660.1 C1661.1 C1662.1 R474.2 U120.11(VOUT) U120.15(VOUT) ; also on sheet 8 15
VCC_0V82_ALTn: R693.2 U120.5(ALT)
VCC_0V82_PG: R705.2 U120.7(PG)
VCC_0V82_SENSE+: C62.1 C1645.2 R561.1 R697.1 R698.1 U120.21(VOSNS+)
VCC_1V20: C718.1 R556.1 U44.6(IN) ; also on sheet 8 14 16
VCC_1V80: R578.1 ; also on sheet 8 14 16
VCC_3V30: C635.1 C636.1 C720.1 L4.2 R411.2 R414.1 R475.2 R546.2 R680.2 R702.1 U44.4(BIAS) ; also on sheet 3 7 8 10 11 13 14 16
VCC_3V30_EN: R682.1 U45.F6(GPIO5) VCC_3V30_EN.1(TP)
VCC_3V30_MON: R680.1 R681.2 U45.B10(VMON6)
VCC_5V00: C59.1 C637.1 C675.1 C676.1 C1647.1 C1648.1 C1649.1 C1650.1 C1651.1 C1652.1 L21.2 R412.1 R464.1 R467.1 R510.1 U34.3(VIN) U120.14(VIN) U120.26(VIN) ; also on sheet 8 13 16
VCC_12V00: D52.K D77.A1(Anode1) D77.A2(Anode2) J84.2 J84.5 R289.2 ; also on sheet 7 8 10
VCC_CORE: C62.2 R575.1 R698.2 ; also on sheet 15
VCCPLL_0V82: C719.1 R544.1 R547.2 R584.1 U44.1(OUT) ; also on sheet 15
ASC_CLK: ASC_CLK.1 U45.G1(ASCCLK)
ASC_RDAT: RDAT.1 U45.E3(RDAT)
ASC_WDAT: U45.H1(WDAT) WDAT.1
ASC_WRCLK: U45.G2(WRCLK) WRCLK.1
EN_core_0V82: C1663.1 R702.2 R703.2 R704.1 R708.1 U120.6(EN)
ICS: C1214.1 C1215.1 U110.17(ICS_1) U110.18(ICS_2) U111.17(ICS_1) U111.18(ICS_2)
IMON1N_082V: U45.H10(IMON1N) ; also on sheet 15
IMON1P_082V: U45.J10(IMON1P) ; also on sheet 15
MPM3695_SCL: R707.2 U120.3(SCL)
MPM3695_SDA: R706.2 U120.4(SDA)
MPM3695_SW1: C1646.1 U120.27(SW) U120.28(SW)
MPM3695_Take: R694.1 R695.2 U120.9(TAKE)
PLL0V82_EN: PLL0V82_EN.1(TP) R715.2 U45.D6(GPIO3)
PLL0V82_MON: R584.2 U45.H8(VMON2)
PLL0V82_MON_GS: R583.2 U45.G8(VMON2GS)
PLL0V82_TRIM: R564.2 U45.C8(TRIM2)
POWER_DOWN: C34.1 R42.2 R80.1 U45.H7(GPIO10)
PTM_DONE: P_DONE.1 U45.C6(PT17D_||_DONE)
PTM_INITN: P_INITN.1 U45.C5(PT17C_||_INITN)
PTM_JTAGENB: J8.2 P_JTAGENB.1 U45.B6(PT15C_||_JTAGENB)
PTM_PROGRAMN: P_PROGN.1 U45.A6(PT15D_||_PROGRAMN)
PTM_SCL_33: PTM_SCL.1 R127.2 R550.1 ; also on sheet 8
PTM_SDA_33: PTM_SDA.1 R126.2 R549.1 ; also on sheet 8
PTM_TCK: J39.8 R77.1 U45.A4(DIO23_||_PT11C_/_TCK)
PTM_TDI: J39.3 R78.2 U45.B3(DIO25_||_PT10D_/_TDI)
PTM_TDO: J39.2 R76.2 U45.A3(DIO22_||_PT10C_/_TDO)
PTM_TMS: J39.6 R79.2 U45.B4(DIO24_||_PT11D_/_TMS)
SB_3V30: C1183.1 C1184.1 J11.1 J39.1 L23.2 R42.1 R76.1 R78.1 R79.1 R81.1 R126.1 R127.1 R566.1 R567.2 R585.2 SB_3V30.1(TP)
SYNC_IN: R615.2 R616.2 U110.3(SYNCIN) U111.16(SYNCO)
SYNC_OUT: U110.16(SYNCO) U111.3(SYNCIN)
USB3_CC1: C1188.1 J25.A5(CC1) R601.2 U109.1
USB3_CC2: C1189.1 J25.B5(CC2) R602.2 U109.2
USB3_LDO_5V: C1190.1 C1191.1 C1261.1 C1268.1 R603.1 R604.1 R605.1 R606.1 R607.1 R608.1 R623.1 R640.2 R649.2 R650.2 R659.1 R660.1 R661.1 R662.1 R675.1 R676.1 U108.10(VIN) U118.6(VOUT)
USB3_PA1: J83.1 R603.2 R663.1 U108.1(PA1)
USB3_PA2: J83.3 R604.2 R664.1 U108.2(PA2)
USB3_PA3: J83.5 R659.2 R665.1 U108.3(PA3)
USB3_PA4: J83.7 R660.2 R666.1 U108.4(PA4)
USB3_PA5: J83.9 R661.2 R667.1 U108.5(PA5)
USB3_PA6: J83.11 R662.2 R668.1 U108.6(PA6)
USB3_PB0: J83.2 R607.2 R671.2 U108.7(PB0)
USB3_PB1: J83.4 R606.2 R672.2 U108.8(PB1)
USB3_PB2: J83.6 R623.2 R651.1 U108.12(PB2)
USB3_PB3: J83.8 R670.2 R675.2 U108.14(PB3)
USB3_PB6: J83.10 R605.2 R673.2 U108.23(PB6)
USB3_PB7: J83.12 R608.2 R674.2 U108.24(PB7)
USB3_PC2: J83.14 R669.2 R676.2 U108.9(PC2)
USB3_RST: C1192.2 U108.22(NRST)
USB_12V: C1204.1 C1205.1 C1206.1 C1207.1 C1208.1 C1209.1 C1210.1 C1211.1 C1666.1 C1667.1 J84.3 J84.6 L24.2 L25.2 R619.2 R622.2
USB_DM: C1186.1 J25.A7(D-A) J25.B7(D-B) R599.1 U109.5
USB_DP: C1187.1 J25.A6(D+A) J25.B6(D+B) R600.1 U109.4
USB_VBUS: C1193.1 C1194.1 C1195.1 C1196.1 C1198.1 C1199.1 C1258.1 C1259.1 C1260.1 C1668.1 J25.A4(VBUS1) J25.A9(VBUS2) J25.B4(VBUS4) J25.B9(VBUS3) R609.1 R610.1 R638.1 R648.1 U110.5(VIN_1) U110.14(VIN_2) U111.5(VIN_1) U111.14(VIN_2) U118.1(VIN)
VLDO_MPM_3V3: C63.1 R52.2 R693.1 R694.2 R705.1 R706.1 R707.1 R708.2 U120.23(VCC)
N21300072: D62.A R411.1
N21300092: C634.1 U34.6(BST)
N21300096: C634.2 L4.1 U34.2(SW)
N21300112: R414.2 R415.1 U34.4(FB)
N21300200: R412.2 R413.1 R682.2 U34.5(EN)
N21332411: C674.2 L21.1 U43.11(LX1) U43.12(LX2)
N21332860: C113.1 C713.1 C714.1 C1182.1 D77.K R519.1 R565.1 R588.1 U43.4(PVIN1) U43.5(PVIN2) U43.6(VIN) U107.3(VIN)
N21333157: C672.1 R463.1 U43.8(COMP)
N21333175: C673.1 R463.2
N21333379: C674.1 U43.13(BOOT)
N21333574: R464.2 R465.1 U43.7(FB)
N21334320: R466.2 U43.1(RT/SYNC)
N21334323: C677.2 U43.9(SS/TR)
N21335874: R467.2 U43.14(PGOOD)
N21392431: D74.A R519.2
N21461634: PS_EN.1(TP) R588.2 R589.1 U43.10(EN)
N21480652: R544.2 R545.1 R563.1 U44.2(ADJ/NC)
N21481605: R556.2 R715.1 U44.3(EN)
N21482339: D75.A R546.1
N21482349: D75.K Q24.C
N21482360: Q24.B R547.1
N21645200: D73.A R510.2
N21945289: C60.1 C61.1 C721.1 C722.1 C723.1 C724.1 C725.1 C1177.1 C1178.1 L3.1 U45.D2(VCCIO3) U45.D5(VCCIO0) U45.D7(VCC) U45.E5(VCCIO0) U45.F2(VCCIO3) U45.F4(VCCIO2) U45.G7(VCC) U45.H4(VCCIO2)
N21945322: J11.2 L3.2 L6.2
N21945422: C726.1 C727.1 C728.1 C729.1 L6.1 U45.E8(VCCA) U45.E9(VCCA) U45.F8(VCCA)
N21948317: C30.2 R549.2 R551.1
N21948373: C29.2 R550.2 R552.1
N21948381: R551.2 U45.C3(SDA)
N21948411: R552.2 U45.C4(SCL)
N21948657: R80.2 SW8.2(B1) SW8.4(B2)
N21993618: R81.2 U45.C1(RESETb)
N22018757: C1180.1 R563.2 R564.1
N22019660: C1181.1 U107.6(BST)
N22019707: C1181.2 L23.1 U107.2(SW)
N22019773: R565.2 R568.1 U107.5(EN) U107_EN.1(TP)
N22019783: R566.2 R569.1 U107.4(FB)
N22019789: D78.A R567.1
N22103220: Q26.D R578.2
N22103236: Q26.G R579.2
N22103439: R579.1 U45.A8(HVOUT1)
N22357147: J8.1 R585.1
N22419042: R398.1 TP_R7.1(TP) U3.R7(VSSR)
N22505657: J25.A8(SBU1) TP26.1(TP)
N22505665: J25.B8(SBU2) TP25.1(TP)
N22506509: R599.2 U108.21(DM)
N22506512: R600.2 U108.20(DP)
N22506572: C1185.1 R648.2 U108.19(VBUS)
N22506942: R601.1 U108.18(CC1)
N22506945: R602.1 U108.17(CC2)
N22513651: R610.2 R613.2 U111.4(EN)
N22518145: R612.2 U110.23(FREQ)
N22518148: R611.2 U111.23(FREQ)
N22519451: C1266.1 R615.1 R618.1 U110.20(VCC)
N22519923: C1267.1 U111.20(VCC)
N22520337: R618.2 U110.1(PG) U110.2(PG)
N22520353: R617.2 U111.1(PG) U111.2(PG)
N22520434: C1203.1 U110.15(BST)
N22520437: C1203.2 L24.1 U110.9(SW_1) U110.10(SW_2)
N22520459: C1202.2 L25.1 U111.9(SW_1) U111.10(SW_2)
N22520465: C1202.1 U111.15(BST)
N22523186: C1667.2 R621.1 R622.1 U111.22(FB)
N22523201: C1666.2 R619.1 R620.1 U110.22(FB)
N22525321: J50.1(+5V) J84.1 J84.4
N22668834: R638.2 R639.2 U118.2(EN)
N22670042: R640.1 R641.1 U118.4(FB)
N22671497: C1265.1 R642.1 R649.1 U111.19(VBIAS)
N22672695: C1264.1 R643.1 R650.1 U110.19(VBIAS)
N23063052: R686.1 U3.W2(VSSR57)
N23070235: C1269.1 R52.1 U120.2(VDRV)
N23070376: C1646.2 U120.25(BST)
N23070416: R695.1 U120.8(PASS)
N23070431: R696.1 U120.19(IREF)
N23070448: R54.2 U120.17(ADDR)
N23076171: C1179.1 R561.2 R562.1
N23077522: D70.A R475.1
N23077532: D70.K Q15.C
N23077534: Q15.B R474.1
N23166257: R609.2 R614.2 U110.4(EN)

Not connected (* = marked no-connect by the designer): J25 A2(TX1+)* A3(TX1-)* A10(RX2-)* A11(RX2+)* B2(TX2+)* B3(TX2-)* B10(RX1-)* B11(RX1+)*; J39 4* 5*; U3 A5(VSSR11)* A6(VSSR12)* A8(VSSR15)* A9(VSSR16)* A11(VSSR19)* A12(VSSR20)* A14(VSSR23)* A15(VSSR24)* A17(VSSR27)* A18(VSSR28)* A20(VSSR31)* A21(VSSR32)* A23(VSSR35)* A24(VSSR36)* A26(VSSR39)* A27(VSSR40)* A29(VSSR43)* A30(VSSR44)* A32(VSSR47)* A33(VSSR48)* B1(VSSR8)* B3(VSSR6)* C1(VSSR7)* C3(VSSR5)* C5(VSSR9)* C6(VSSR10)* C8(VSSR13)* C9(VSSR14)* C11(VSSR17)* C12(VSSR18)* C14(VSSR21)* C15(VSSR22)* C17(VSSR25)* C18(VSSR26)* C20(VSSR29)* C21(VSSR30)* C23(VSSR33)* C24(VSSR34)* C26(VSSR37)* C27(VSSR38)* C29(VSSR41)* C30(VSSR42)* C32(VSSR45)* C33(VSSR46)* E1(VSSR4)* E3(VSSR2)* E5(NC52)* E6(NC51)* E8(NC48)* E9(NC47)* E11(NC43)* E12(NC42)* E14(NC39)* E15(NC38)* E17(NC34)* E18(NC33)* E20(NC30)* E21(NC29)* E23(NC25)* E24(NC24)* E26(NC21)* E27(NC20)* E29(NC16)* E30(NC15)* E32(NC12)* E33(NC11)* F1(VSSR3)* F3(VSSR1)* G5(NC54)* G6(NC53)* G8(NC50)* G9(NC49)* G11(NC45)* G12(NC44)* G14(NC41)* G15(NC40)* G17(NC36)* G18(NC35)* G20(NC32)* G21(NC31)* G23(NC27)* G24(NC26)* G26(NC23)* G27(NC22)* G29(NC18)* G30(NC17)* G32(NC14)* G33(NC13)* H1(NC56)* H3(NC58)* J1(NC57)* J3(NC59)* J6(NC46)* J12(NC37)* J18(NC28)* J24(NC19)* J30(NC10)* L1(NC60)* L3(NC62)* L26(NC1)* L28(NC9)* L30(NC7)* L32(VSSR49)* L34(VSSR51)* M1(NC61)* M3(NC63)* M6(NC55)* M28(NC8)* M30(NC6)* M32(VSSR50)* M34(VSSR52)* P28(NC5)* P30(NC3)* P32(VSSR53)* P34(VSSR55)* R28(NC4)* R30(NC2)* R32(VSSR54)* R34(VSSR56)*; U45 A2(DIO16_/_WDAT_3_||_PL3C)* A5(DIO8_||_PT12A_/_PCLKT0_1)* A7(HVOUT2)* A9(TRIM4)* B1(DIO15_/_WRCLK_3_||_PL3A_/_PCLKT3_2)* B2(RDAT_3_/_I2C_ADDR2_||_PL3D)* B5(DIO9_||_PT12B_/_PCLKC0_1)* B7(GPIO1)* C2(DIO11_/_WRCLK_1_||_PL5A_/_PCLKT3_1)* C9(VMON8)* D1(DIO13_/_WRCLK_2_||_PL4B)* D3(RDAT_1_/_I2C_ADDR0_||_PL5B_/_PCLKC3_1)* D4(DIO10_||_PT11A)* D9(VMON7)* E1(RDAT_2_/_I2C_ADDR1_||_PL4C)* E4(DIO7_||_PB15B)* E10(VMON4)* F1(DIO14_/_WDAT_2_||_PL4D)* F3(DIO6_||_PB15A)* F5(GPIO6)* F10(TMON1N)* G3(DIO5_||_PB9A_/_PCLKT2_0)* G5(HVOUT3)* G6(GPIO7)* G9(HIMONN_HVMON)* G10(TMON1P)* H2(DIO12_/_WDAT_1_||_PL8C)* H3(DIO4_||_PB9B_/_PCLKC2_0)* H5(HVOUT4)* H6(GPIO8)* H9(HVIMONP)* J1(NC)* J2(DIO19_/_RST_3_||_PB4C_/_CSSPIN)* J3(DIO20_||_PB6C_/_MCLK/CCLK)* J4(DIO3_||_PB20A)* J5(DIO21_||_PB20C_/_SN/MDS/SCA)* J6(GPIO9)* J9(TMON2N)* K2(DIO18_/_RST_2_||_PB6D_/_SO_/_SPISO)* K3(DIO1_||_PB11B_/_PCLKC2_1)* K4(DIO2_||_PB11A_/_PCLKT2_1)* K5(DIO17_/_RST_1_||_PB20D_/_SI_/_SIPI)* K9(TMON2P)*; U108 13(NC1)* 15(NC2)* 16(NC3)*; U110 6(NC_1)* 13(NC_2)*; U111 6(NC_1)* 13(NC_2)*; U118 5(NC)*; U120 10(SET)* 16(NC_1)* 18(ISUM)* 24(NC_2)*

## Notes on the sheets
sheet 17
- 12V INPUT
- Output = 5.00V/6A
- Output = 3.30V/2A
- 12V to 5V
- 5V-3.3V
- Output = 3.30V/2A
- 12V-3.3V
- Vout = (0.6/2000) * (2000 + 732) = 0.8196V
- Polymer Tantalum
- Output = 0.82V/0.5A
- Polymer Tantalum
- Place R583 & R584
  near Avant.
- Connect back from the remote
  FPGA VCC_CORE_0V82 Power PIN
  & GND PIN as a differential trace
- 0.1%,Thin Film
- Place R575 & R576
  near Avant.
- PMBUS ADDR : 0x30h
sheet 19
- DEFAULT:
  OPEN
sheet 20
- 100W-20V@5A
- Voutput = (R619/620+1)*0.6=12.06V
- Voutput = (R622/621+1)*0.6=12.06V
- Voutput = (R640/641+1)*1.215=5.0544V
